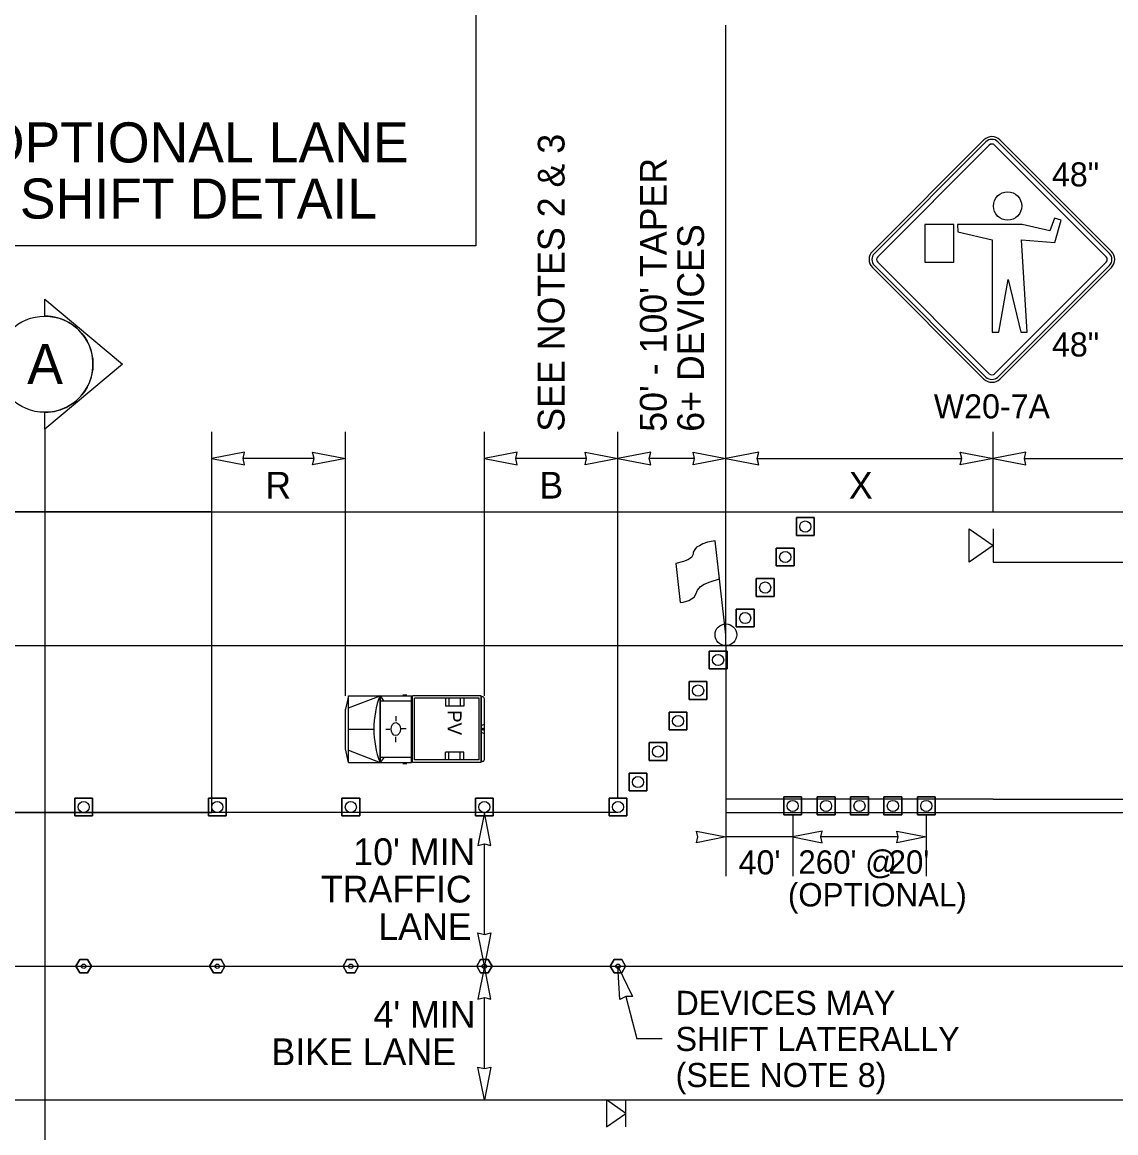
# Model space of a CAD drawing. Extents: x 99999.1 to 100095.7, y 99995 to 100010.7.
# Drawn here: x 100049.366 to 100052.641, y 100005.634 to 100008.958 of the extents above; entities that cross this region are included whole.
import ezdxf

# ---------------------------------------------------------------- set-up
doc = ezdxf.new("R2010")
doc.units = 0
for name, color, linetype in [('RD_ED_ShoulderPavedEdge', 7, 'Continuous'), ('RD_MK_LineDblYellowCenter', 7, 'Continuous'), ('RD_MK_LineEdgeWhite', 7, 'Continuous'), ('RD_MK_LineNoPass', 7, 'Continuous'), ('RD_MK_LineSkipCenter', 7, 'Continuous'), ('SH_DE_DetailHeading2Text', 7, 'Continuous'), ('SH_GI_SectionCut', 7, 'Continuous'), ('SH_TI_Tables', 7, 'Continuous'), ('TR_SN_ConstructionSigns', 7, 'Continuous'), ('TR_WZ_FlaggingStation', 7, 'Continuous'), ('TR_WZ_PortableSignMountBlk-Org', 7, 'Continuous'), ('TR_WZ_PortableSignMountBlk-Wht', 7, 'Continuous'), ('TR_WZ_ProtectiveVehicle', 7, 'Continuous'), ('TR_WZ_TrafficCone', 7, 'Continuous'), ('TR_WZ_TubularMarker', 7, 'Continuous'), ('TR_WZ_WorkZoneDetails', 7, 'Continuous'), ('TR_WZ_WorkZoneTextCurrent', 7, 'Continuous')]:
    doc.layers.add(name, color=color, linetype=linetype)

msp = doc.modelspace()

# ---------------------------------------------------------------- linework, layer by layer
at = {"layer": 'RD_ED_ShoulderPavedEdge'}
for p, q in [((100040.1076, 100007.4923), (100055.6424, 100007.4923)), ((100040.1076, 100005.7323), (100055.6424, 100005.7323))]:
    msp.add_line(p, q, dxfattribs=at)
at = {"layer": 'RD_MK_LineDblYellowCenter'}
for p, q in [((100052.2733, 100006.6323), (100055.6631, 100006.6323)), ((100052.2733, 100006.5923), (100055.6218, 100006.5923))]:
    msp.add_line(p, q, dxfattribs=at)
at = {"layer": 'RD_MK_LineEdgeWhite'}
for p, q in [((100040.1076, 100007.0923), (100055.6424, 100007.0923)), ((100040.1076, 100006.1323), (100055.6424, 100006.1323))]:
    msp.add_line(p, q, dxfattribs=at)
at = {"layer": 'RD_MK_LineNoPass'}
msp.add_line((100051.4733, 100006.5923), (100052.2733, 100006.5923), dxfattribs=at)
at = {"layer": 'RD_MK_LineSkipCenter'}
for points in [[(100052.2733, 100006.6323), (100051.4733, 100006.6323)], [(100051.15, 100006.5923), (100043.4767, 100006.5923)]]:
    msp.add_lwpolyline(points, dxfattribs=at)
at = {"layer": 'SH_GI_SectionCut'}
for p, q in [((100049.4337, 100008.0785), (100049.4337, 100008.1294)), ((100049.4337, 100008.1294), (100049.6664, 100007.9345)), ((100049.6664, 100007.9345), (100049.4337, 100007.7396)), ((100049.4337, 100007.7396), (100049.4337, 100007.7905)), ((100049.4338, 100007.7396), (100049.4338, 100005.4996))]:
    msp.add_line(p, q, dxfattribs=at)
msp.add_circle((100049.4338, 100007.9345), 0.144, dxfattribs=at)
msp.add_arc((100049.4338, 100007.9345), 0.144, 269.9978, 90.0022, dxfattribs=at)
at = {"layer": 'SH_TI_Tables'}
msp.add_lwpolyline([(100045.2702, 100010.325), (100050.7241, 100010.325), (100050.7241, 100008.2892), (100045.2702, 100008.2892)], close=True, dxfattribs=at)
at = {"layer": 'TR_SN_ConstructionSigns'}
for p, q in [((100052.2461, 100008.6062), (100051.912, 100008.2721)), ((100052.6279, 100008.2721), (100052.2938, 100008.6062)), ((100052.2521, 100008.6002), (100051.918, 100008.2661)), ((100051.9279, 100008.2561), (100052.262, 100008.5903)), ((100052.2779, 100008.5903), (100052.612, 100008.2561)), ((100052.622, 100008.2661), (100052.2879, 100008.6002)), ((100052.262, 100007.9061), (100051.9279, 100008.2402)), ((100052.612, 100008.2402), (100052.2779, 100007.9061)), ((100051.912, 100008.2243), (100052.2461, 100007.8902)), ((100051.918, 100008.2303), (100052.2521, 100007.8962)), ((100052.2879, 100007.8962), (100052.622, 100008.2303)), ((100052.2938, 100007.8902), (100052.6279, 100008.2243))]:
    msp.add_line(p, q, dxfattribs=at)
for points in [[(100052.1666, 100008.3526), (100052.1679, 100008.3309), (100052.2705, 100008.307), (100052.2705, 100008.0307), (100052.2905, 100008.0307), (100052.3187, 100008.1877), (100052.3562, 100008.0307), (100052.3752, 100008.0307), (100052.3585, 100008.3069), (100052.4588, 100008.2988), (100052.4777, 100008.3658), (100052.457, 100008.3717), (100052.4438, 100008.3334), (100052.3609, 100008.3526)], [(100052.0687, 100008.3523), (100052.0687, 100008.2401), (100052.1563, 100008.2401), (100052.1563, 100008.3523)]]:
    msp.add_lwpolyline(points, close=True, dxfattribs=at)
msp.add_circle((100052.3169, 100008.4081), 0.0424, dxfattribs=at)
for centre, radius, start, end in [((100052.27, 100008.5823), 0.0338, 45, 135), ((100052.27, 100008.5823), 0.0253, 45, 135), ((100052.27, 100008.5823), 0.0113, 45, 135), ((100051.9359, 100008.2482), 0.0338, 135, 225), ((100052.6041, 100008.2482), 0.0338, 315, 45), ((100051.9359, 100008.2482), 0.0253, 135, 225), ((100051.9359, 100008.2482), 0.0113, 135, 225), ((100052.6041, 100008.2482), 0.0113, 315, 45), ((100052.6041, 100008.2482), 0.0253, 315, 45), ((100052.27, 100007.9141), 0.0113, 225, 315), ((100052.27, 100007.9141), 0.0338, 225, 315), ((100052.27, 100007.9141), 0.0253, 225, 315)]:
    msp.add_arc(centre, radius, start, end, dxfattribs=at)
at = {"layer": 'TR_WZ_FlaggingStation'}
for p, q in [((100051.4543, 100007.2917), (100051.4413, 100007.4061)), ((100051.4733, 100007.1248), (100051.4413, 100007.4058)), ((100051.3233, 100007.3383), (100051.3366, 100007.2211)), ((100051.4543, 100007.2917), (100051.4543, 100007.2917))]:
    msp.add_line(p, q, dxfattribs=at)
for points in [[(100051.4413, 100007.4061), (100051.4355, 100007.4048), (100051.4177, 100007.4014), (100051.4039, 100007.3972), (100051.3942, 100007.3911), (100051.3857, 100007.3864), (100051.38, 100007.3796), (100051.3757, 100007.3717), (100051.3752, 100007.3655), (100051.3698, 100007.3563), (100051.359, 100007.3489), (100051.3466, 100007.3437), (100051.3233, 100007.3383)], [(100051.3366, 100007.2211), (100051.3448, 100007.2225), (100051.3624, 100007.2271), (100051.3781, 100007.2376), (100051.3846, 100007.2482), (100051.3885, 100007.2585), (100051.3976, 100007.2694), (100051.4086, 100007.2756), (100051.4259, 100007.2827), (100051.4543, 100007.2917)]]:
    msp.add_lwpolyline(points, dxfattribs=at)
msp.add_circle((100051.4733, 100007.1248), 0.0325, dxfattribs=at)
at = {"layer": 'TR_WZ_PortableSignMountBlk-Org'}
msp.add_line((100052.2733, 100007.4422), (100052.2733, 100007.3422), dxfattribs=at)
msp.add_lwpolyline([(100052.2733, 100007.3923), (100052.2015, 100007.3422), (100052.2015, 100007.4422)], close=True, dxfattribs=at)
at = {"layer": 'TR_WZ_PortableSignMountBlk-Wht'}
msp.add_line((100051.1733, 100005.6519), (100051.1733, 100005.7323), dxfattribs=at)
msp.add_lwpolyline([(100051.1733, 100005.692), (100051.1156, 100005.7323), (100051.1156, 100005.6519)], close=True, dxfattribs=at)
at = {"layer": 'TR_WZ_ProtectiveVehicle'}
for p, q in [((100050.343, 100006.9423), (100050.3338, 100006.902)), ((100050.343, 100006.7423), (100050.343, 100006.9423)), ((100050.343, 100006.9423), (100050.5319, 100006.9423)), ((100050.343, 100006.9057), (100050.4375, 100006.9423)), ((100050.4375, 100006.7423), (100050.4375, 100006.9423)), ((100050.4392, 100006.7423), (100050.4392, 100006.9423)), ((100050.4492, 100006.9268), (100050.4392, 100006.9423)), ((100050.5062, 100006.9451), (100050.5175, 100006.9451)), ((100050.5319, 100006.7423), (100050.5319, 100006.9423)), ((100050.7404, 100006.9423), (100050.5347, 100006.9423)), ((100050.5347, 100006.7423), (100050.5347, 100006.9423)), ((100050.7404, 100006.7423), (100050.7404, 100006.9423)), ((100050.4392, 100006.9268), (100050.5319, 100006.9268)), ((100050.7346, 100006.9344), (100050.5405, 100006.9344)), ((100050.5405, 100006.7503), (100050.5405, 100006.9344)), ((100050.6332, 100006.9344), (100050.6332, 100006.9113)), ((100050.6882, 100006.9113), (100050.6332, 100006.9113)), ((100050.6432, 100006.9344), (100050.6432, 100006.9113)), ((100050.6772, 100006.9344), (100050.6772, 100006.9113)), ((100050.6882, 100006.9344), (100050.6882, 100006.9113)), ((100050.7346, 100006.7503), (100050.7346, 100006.9344)), ((100050.7456, 100006.939), (100050.7411, 100006.939)), ((100050.7411, 100006.7456), (100050.7411, 100006.939)), ((100050.75, 100006.7517), (100050.75, 100006.9329)), ((100050.3338, 100006.7827), (100050.3338, 100006.902)), ((100050.4852, 100006.8808), (100050.485, 100006.8658)), ((100050.343, 100006.8423), (100050.4189, 100006.8423)), ((100050.4544, 100006.8422), (100050.467, 100006.8423)), ((100050.4986, 100006.8427), (100050.4986, 100006.8427)), ((100050.5154, 100006.8431), (100050.5005, 100006.8427)), ((100050.75, 100006.8564), (100050.7411, 100006.8527)), ((100050.7476, 100006.8423), (100050.7435, 100006.8423)), ((100050.7456, 100006.8395), (100050.7456, 100006.8451)), ((100050.4845, 100006.8027), (100050.4845, 100006.8188)), ((100050.75, 100006.8282), (100050.7411, 100006.832)), ((100050.343, 100006.7423), (100050.3338, 100006.7827)), ((100050.343, 100006.779), (100050.4375, 100006.7423)), ((100050.343, 100006.7423), (100050.5319, 100006.7423)), ((100050.4392, 100006.7423), (100050.4512, 100006.7578)), ((100050.4392, 100006.7578), (100050.5319, 100006.7578)), ((100050.7404, 100006.7423), (100050.5347, 100006.7423)), ((100050.7346, 100006.7503), (100050.5405, 100006.7503)), ((100050.6882, 100006.7733), (100050.6332, 100006.7733)), ((100050.6332, 100006.7503), (100050.6332, 100006.7733)), ((100050.6432, 100006.7503), (100050.6432, 100006.7733)), ((100050.6772, 100006.7503), (100050.6772, 100006.7733)), ((100050.6882, 100006.7503), (100050.6882, 100006.7733)), ((100050.7456, 100006.7456), (100050.7411, 100006.7456)), ((100050.5062, 100006.7395), (100050.5175, 100006.7395))]:
    msp.add_line(p, q, dxfattribs=at)
for centre, major_axis, start_param, end_param in [((100050.5725, 100006.8424), (0, -0.2099), 4.215852, 5.209111), ((100050.7456, 100006.9329), (0, 0.0061), 4.712389, 6.283185), ((100050.7456, 100006.7517), (0, -0.0061), 6.283185, 7.853982)]:
    msp.add_ellipse(centre, major_axis=major_axis, ratio=0.73155, start_param=start_param, end_param=end_param, dxfattribs=at)
for centre, major_axis in [((100050.4845, 100006.8423), (0, 0.0193)), ((100050.7456, 100006.8423), (0, 0.00282))]:
    msp.add_ellipse(centre, major_axis=major_axis, ratio=0.73155, dxfattribs=at)
at = {"layer": 'TR_WZ_TrafficCone'}
for points in [[(100051.6843, 100007.4753), (100051.7376, 100007.4753), (100051.7376, 100007.422), (100051.6843, 100007.422), (100051.6843, 100007.4753)], [(100051.6843, 100007.422), (100051.7376, 100007.422), (100051.7376, 100007.4753), (100051.6843, 100007.4753), (100051.6843, 100007.422)], [(100051.6243, 100007.384), (100051.6776, 100007.384), (100051.6776, 100007.3306), (100051.6243, 100007.3306), (100051.6243, 100007.384)], [(100051.6243, 100007.3306), (100051.6776, 100007.3306), (100051.6776, 100007.384), (100051.6243, 100007.384), (100051.6243, 100007.3306)], [(100051.5643, 100007.2926), (100051.6176, 100007.2926), (100051.6176, 100007.2393), (100051.5643, 100007.2393), (100051.5643, 100007.2926)], [(100051.5643, 100007.2393), (100051.6176, 100007.2393), (100051.6176, 100007.2926), (100051.5643, 100007.2926), (100051.5643, 100007.2393)], [(100051.5043, 100007.2013), (100051.5576, 100007.2013), (100051.5576, 100007.148), (100051.5043, 100007.148), (100051.5043, 100007.2013)], [(100051.5043, 100007.148), (100051.5576, 100007.148), (100051.5576, 100007.2013), (100051.5043, 100007.2013), (100051.5043, 100007.148)], [(100051.4766, 100007.0757), (100051.4233, 100007.0757), (100051.4233, 100007.0224), (100051.4766, 100007.0224), (100051.4766, 100007.0757)], [(100051.4766, 100007.0224), (100051.4233, 100007.0224), (100051.4233, 100007.0757), (100051.4766, 100007.0757), (100051.4766, 100007.0224)], [(100051.4166, 100006.9844), (100051.3633, 100006.9844), (100051.3633, 100006.9311), (100051.4166, 100006.9311), (100051.4166, 100006.9844)], [(100051.4166, 100006.9311), (100051.3633, 100006.9311), (100051.3633, 100006.9844), (100051.4166, 100006.9844), (100051.4166, 100006.9311)], [(100051.3566, 100006.8931), (100051.3033, 100006.8931), (100051.3033, 100006.8397), (100051.3566, 100006.8397), (100051.3566, 100006.8931)], [(100051.3566, 100006.8397), (100051.3033, 100006.8397), (100051.3033, 100006.8931), (100051.3566, 100006.8931), (100051.3566, 100006.8397)], [(100051.2966, 100006.8017), (100051.2433, 100006.8017), (100051.2433, 100006.7484), (100051.2966, 100006.7484), (100051.2966, 100006.8017)], [(100051.2966, 100006.7484), (100051.2433, 100006.7484), (100051.2433, 100006.8017), (100051.2966, 100006.8017), (100051.2966, 100006.7484)], [(100051.2366, 100006.7104), (100051.1833, 100006.7104), (100051.1833, 100006.6571), (100051.2366, 100006.6571), (100051.2366, 100006.7104)], [(100051.2366, 100006.6571), (100051.1833, 100006.6571), (100051.1833, 100006.7104), (100051.2366, 100006.7104), (100051.2366, 100006.6571)], [(100049.5234, 100006.6357), (100049.5767, 100006.6357), (100049.5767, 100006.5823), (100049.5234, 100006.5823), (100049.5234, 100006.6357)], [(100049.5234, 100006.5823), (100049.5767, 100006.5823), (100049.5767, 100006.6357), (100049.5234, 100006.6357), (100049.5234, 100006.5823)], [(100049.9234, 100006.6357), (100049.9767, 100006.6357), (100049.9767, 100006.5823), (100049.9234, 100006.5823), (100049.9234, 100006.6357)], [(100049.9234, 100006.5823), (100049.9767, 100006.5823), (100049.9767, 100006.6357), (100049.9234, 100006.6357), (100049.9234, 100006.5823)], [(100050.3234, 100006.6357), (100050.3767, 100006.6357), (100050.3767, 100006.5823), (100050.3234, 100006.5823), (100050.3234, 100006.6357)], [(100050.3234, 100006.5823), (100050.3767, 100006.5823), (100050.3767, 100006.6357), (100050.3234, 100006.6357), (100050.3234, 100006.5823)], [(100050.7234, 100006.6357), (100050.7767, 100006.6357), (100050.7767, 100006.5823), (100050.7234, 100006.5823), (100050.7234, 100006.6357)], [(100050.7234, 100006.5823), (100050.7767, 100006.5823), (100050.7767, 100006.6357), (100050.7234, 100006.6357), (100050.7234, 100006.5823)], [(100051.1766, 100006.6357), (100051.1233, 100006.6357), (100051.1233, 100006.5823), (100051.1766, 100006.5823), (100051.1766, 100006.6357)], [(100051.1766, 100006.5823), (100051.1233, 100006.5823), (100051.1233, 100006.6357), (100051.1766, 100006.6357), (100051.1766, 100006.5823)], [(100051.7, 100006.639), (100051.6467, 100006.639), (100051.6467, 100006.5857), (100051.7, 100006.5857), (100051.7, 100006.639)], [(100051.7, 100006.5857), (100051.6467, 100006.5857), (100051.6467, 100006.639), (100051.7, 100006.639), (100051.7, 100006.5857)], [(100051.8, 100006.639), (100051.7467, 100006.639), (100051.7467, 100006.5857), (100051.8, 100006.5857), (100051.8, 100006.639)], [(100051.8, 100006.5857), (100051.7467, 100006.5857), (100051.7467, 100006.639), (100051.8, 100006.639), (100051.8, 100006.5857)], [(100051.9, 100006.639), (100051.8467, 100006.639), (100051.8467, 100006.5857), (100051.9, 100006.5857), (100051.9, 100006.639)], [(100051.9, 100006.5857), (100051.8467, 100006.5857), (100051.8467, 100006.639), (100051.9, 100006.639), (100051.9, 100006.5857)], [(100052, 100006.639), (100051.9467, 100006.639), (100051.9467, 100006.5857), (100052, 100006.5857), (100052, 100006.639)], [(100052, 100006.5857), (100051.9467, 100006.5857), (100051.9467, 100006.639), (100052, 100006.639), (100052, 100006.5857)], [(100052.1, 100006.639), (100052.0467, 100006.639), (100052.0467, 100006.5857), (100052.1, 100006.5857), (100052.1, 100006.639)], [(100052.1, 100006.5857), (100052.0467, 100006.5857), (100052.0467, 100006.639), (100052.1, 100006.639), (100052.1, 100006.5857)]]:
    msp.add_lwpolyline(points, dxfattribs=at)
for centre in [(100051.7109, 100007.4486), (100051.6509, 100007.3573), (100051.5909, 100007.266), (100051.5309, 100007.1746), (100051.45, 100007.0491), (100051.39, 100006.9577), (100051.33, 100006.8664), (100051.27, 100006.7751), (100051.21, 100006.6837), (100049.55, 100006.609), (100049.95, 100006.609), (100050.35, 100006.609), (100050.75, 100006.609), (100051.15, 100006.609), (100051.6733, 100006.6123), (100051.7733, 100006.6123), (100051.8733, 100006.6123), (100051.9733, 100006.6123), (100052.0733, 100006.6123)]:
    msp.add_circle(centre, 0.0167, dxfattribs=at)
at = {"layer": 'TR_WZ_TubularMarker'}
for points in [[(100049.5269, 100006.1323), (100049.5385, 100006.1523), (100049.5616, 100006.1523), (100049.5731, 100006.1323), (100049.5616, 100006.1123), (100049.5385, 100006.1123)], [(100049.9269, 100006.1323), (100049.9385, 100006.1523), (100049.9616, 100006.1523), (100049.9731, 100006.1323), (100049.9616, 100006.1123), (100049.9385, 100006.1123)], [(100050.3269, 100006.1323), (100050.3385, 100006.1523), (100050.3616, 100006.1523), (100050.3731, 100006.1323), (100050.3616, 100006.1123), (100050.3385, 100006.1123)], [(100050.7269, 100006.1323), (100050.7385, 100006.1523), (100050.7616, 100006.1523), (100050.7731, 100006.1323), (100050.7616, 100006.1123), (100050.7385, 100006.1123)], [(100051.1269, 100006.1323), (100051.1384, 100006.1523), (100051.1615, 100006.1523), (100051.1731, 100006.1323), (100051.1615, 100006.1123), (100051.1384, 100006.1123)]]:
    msp.add_lwpolyline(points, close=True, dxfattribs=at)
for points in [[(100049.5385, 100006.1123), (100049.5616, 100006.1123), (100049.5731, 100006.1323), (100049.5616, 100006.1523), (100049.5385, 100006.1523), (100049.5269, 100006.1323), (100049.5385, 100006.1123)], [(100049.9385, 100006.1123), (100049.9616, 100006.1123), (100049.9731, 100006.1323), (100049.9616, 100006.1523), (100049.9385, 100006.1523), (100049.9269, 100006.1323), (100049.9385, 100006.1123)], [(100050.3385, 100006.1123), (100050.3616, 100006.1123), (100050.3731, 100006.1323), (100050.3616, 100006.1523), (100050.3385, 100006.1523), (100050.3269, 100006.1323), (100050.3385, 100006.1123)], [(100050.7385, 100006.1123), (100050.7616, 100006.1123), (100050.7731, 100006.1323), (100050.7616, 100006.1523), (100050.7385, 100006.1523), (100050.7269, 100006.1323), (100050.7385, 100006.1123)], [(100051.1384, 100006.1123), (100051.1615, 100006.1123), (100051.1731, 100006.1323), (100051.1615, 100006.1523), (100051.1384, 100006.1523), (100051.1269, 100006.1323), (100051.1384, 100006.1123)]]:
    msp.add_lwpolyline(points, dxfattribs=at)
for centre in [(100049.55, 100006.1323), (100049.95, 100006.1323), (100050.35, 100006.1323), (100050.75, 100006.1323), (100051.15, 100006.1323)]:
    msp.add_circle(centre, 0.00667, dxfattribs=at)
at = {"layer": 'TR_WZ_WorkZoneDetails'}
for p, q in [((100051.4733, 100007.0923), (100051.4733, 100008.9491)), ((100049.9338, 100007.4923), (100049.9338, 100007.7323)), ((100050.3338, 100006.9423), (100050.3338, 100007.7323)), ((100050.75, 100006.9423), (100050.75, 100007.7323)), ((100051.15, 100006.6357), (100051.15, 100007.7323)), ((100052.2733, 100007.4923), (100052.2733, 100007.7323)), ((100050.24, 100007.6523), (100050.0275, 100007.6523)), ((100051.0563, 100007.6523), (100050.8437, 100007.6523)), ((100051.3796, 100007.6523), (100051.2437, 100007.6523)), ((100051.5671, 100007.6523), (100052.1796, 100007.6523)), ((100052.3671, 100007.6523), (100052.9796, 100007.6523)), ((100052.2733, 100007.3422), (100054.6733, 100007.3422)), ((100051.4733, 100007.0923), (100051.4733, 100006.4023)), ((100051.6733, 100006.5857), (100051.6733, 100006.4023)), ((100052.0733, 100006.5857), (100052.0733, 100006.4023)), ((100051.6733, 100006.5193), (100051.4733, 100006.5193)), ((100051.989, 100006.5193), (100051.7577, 100006.5193)), ((100050.75, 100006.2278), (100050.75, 100006.4986)), ((100050.75, 100005.8261), (100050.75, 100006.0386)), ((100051.1735, 100006.0416), (100051.2064, 100005.9148)), ((100051.2826, 100005.9148), (100051.2064, 100005.9148))]:
    msp.add_line(p, q, dxfattribs=at)
for points in [[(100049.9338, 100007.6523), (100050.032, 100007.6331), (100050.0275, 100007.6523), (100050.032, 100007.6716)], [(100050.3338, 100007.6523), (100050.2355, 100007.6331), (100050.24, 100007.6523), (100050.2355, 100007.6716)], [(100050.75, 100007.6523), (100050.8483, 100007.6331), (100050.8437, 100007.6523), (100050.8483, 100007.6716)], [(100051.15, 100007.6523), (100051.0517, 100007.6331), (100051.0563, 100007.6523), (100051.0517, 100007.6716)], [(100051.15, 100007.6523), (100051.2483, 100007.6331), (100051.2437, 100007.6523), (100051.2483, 100007.6716)], [(100051.4733, 100007.6523), (100051.3751, 100007.6331), (100051.3796, 100007.6523), (100051.3751, 100007.6716)], [(100051.4733, 100007.6523), (100051.5716, 100007.6331), (100051.5671, 100007.6523), (100051.5716, 100007.6716)], [(100052.2733, 100007.6523), (100052.1751, 100007.6331), (100052.1796, 100007.6523), (100052.1751, 100007.6716)], [(100052.2733, 100007.6523), (100052.3716, 100007.6331), (100052.3671, 100007.6523), (100052.3716, 100007.6716)], [(100045.15, 100007.4923), (100045.15, 100006.5923), (100049.9338, 100006.5923), (100049.9338, 100007.4923)], [(100050.75, 100006.5923), (100050.7307, 100006.4941), (100050.75, 100006.4986), (100050.7692, 100006.4941)], [(100051.4733, 100006.5193), (100051.3849, 100006.502), (100051.389, 100006.5193), (100051.3849, 100006.5367)], [(100051.6733, 100006.5193), (100051.7618, 100006.502), (100051.7577, 100006.5193), (100051.7618, 100006.5367)], [(100052.0733, 100006.5193), (100051.9849, 100006.502), (100051.989, 100006.5193), (100051.9849, 100006.5367)], [(100050.75, 100006.1341), (100050.7307, 100006.2324), (100050.75, 100006.2278), (100050.7692, 100006.2324)], [(100050.75, 100006.1323), (100050.7307, 100006.0341), (100050.75, 100006.0386), (100050.7693, 100006.0341)], [(100051.15, 100006.1323), (100051.1933, 100006.042), (100051.1735, 100006.0416), (100051.156, 100006.0324)], [(100050.75, 100005.7323), (100050.7307, 100005.8306), (100050.75, 100005.8261), (100050.7693, 100005.8306)]]:
    msp.add_lwpolyline(points, close=True, dxfattribs=at)

# ---------------------------------------------------------------- texts
at = {"layer": 'SH_DE_DetailHeading2Text'}
for s, p in [('OPTIONAL LANE', (100049.248, 100008.5384)), ('SHIFT DETAIL', (100049.3589, 100008.3704))]:
    msp.add_text(s, height=0.12, rotation=360, dxfattribs=at).set_placement(p)
at = {"layer": 'SH_GI_SectionCut'}
msp.add_text('A', height=0.12, rotation=359.99, dxfattribs=at).set_placement((100049.3809, 100007.8754))
at = {"layer": 'TR_SN_ConstructionSigns'}
for s, p in [('48"', (100052.4498, 100008.4667)), ('48"', (100052.4498, 100007.9576)), ('W20-7A', (100052.096, 100007.7723))]:
    msp.add_text(s, height=0.072, rotation=360, dxfattribs=at).set_placement(p)
at = {"layer": 'TR_WZ_ProtectiveVehicle'}
msp.add_text('PV', height=0.04175, rotation=270, dxfattribs=at).set_placement((100050.6398, 100006.899))
at = {"layer": 'TR_WZ_WorkZoneTextCurrent'}
for s, p in [('SEE NOTES 2 & 3', (100050.99, 100007.7323)), ("50' - 100' TAPER", (100051.2957, 100007.7323)), ('6+ DEVICES', (100051.4077, 100007.7323))]:
    msp.add_text(s, height=0.08, rotation=90, dxfattribs=at).set_placement(p)
for s, height, p in [('R', 0.08, (100050.0939, 100007.5323)), ('B', 0.08, (100050.9145, 100007.5323)), ('X', 0.08, (100051.8416, 100007.5323)), ("10' MIN", 0.08, (100050.3575, 100006.4352)), ("40'", 0.072, (100051.5114, 100006.4073)), ("260' @", 0.07, (100051.6903, 100006.4093)), ("20'", 0.07, (100051.9604, 100006.4093)), ('TRAFFIC', 0.08, (100050.2603, 100006.3232)), ('(OPTIONAL)', 0.07, (100051.659, 100006.3113)), ('LANE', 0.08, (100050.4322, 100006.2112)), ('DEVICES MAY', 0.072, (100051.3226, 100005.9868)), ("4' MIN", 0.08, (100050.4179, 100005.9483)), ('SHIFT LATERALLY', 0.072, (100051.3226, 100005.8788)), ('BIKE LANE', 0.08, (100050.1122, 100005.8363)), ('(SEE NOTE 8)', 0.072, (100051.3226, 100005.7708))]:
    msp.add_text(s, height=height, dxfattribs=at).set_placement(p)

doc.saveas('drawing.dxf')
